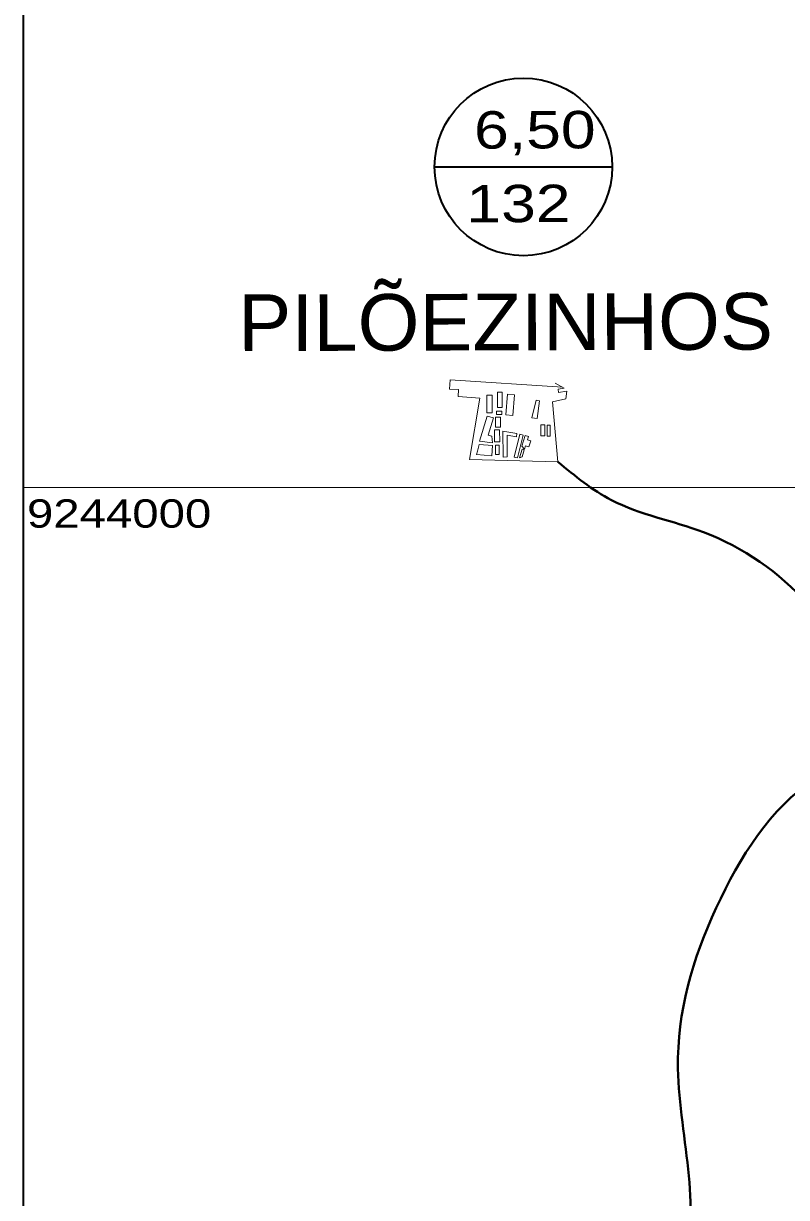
# Model space of a CAD drawing. Extents: x -4 to 42046, y -3 to 29697.
# Drawn here: x 23908 to 25194, y 13596 to 15575 of the extents above; entities that cross this region are included whole.
import ezdxf
from ezdxf.enums import TextEntityAlignment as Align

# ---------------------------------------------------------------- set-up
doc = ezdxf.new("R2010")
doc.units = 0
doc.header["$LTSCALE"] = 32
doc.linetypes.add('DOT_DASHED', pattern=[7.7, 5, -1.2, 0.3, -1.2])
for name, color, linetype, lineweight in [('1', 7, 'DOT_DASHED', 13), ('6', 7, 'Continuous', 40), ('63', 7, 'Continuous', 25), ('8', 7, 'Continuous', 35), ('9', 7, 'Continuous', 40)]:
    doc.layers.add(name, color=color, linetype=linetype, lineweight=lineweight)

msp = doc.modelspace()

# ---------------------------------------------------------------- linework, layer by layer
at = {"layer": '1', "linetype": 'Continuous'}
msp.add_lwpolyline([(24803.67, 14968.73), (24819.25, 14960.43), (24808.72, 14958.85), (24809.58, 14953.13), (24823.73, 14955.25), (24821.79, 14942.77), (24799.17, 14937.74), (24808.46, 14836.4), (24659.35, 14840.3), (24676.71, 14943.88), (24640.44, 14946.26), (24641.21, 14958.03), (24625.88, 14959.03), (24626.88, 14974.34), (24816.4, 14961.95)], dxfattribs=at)
for points in [[(24688.88, 14918.81), (24688.79, 14948.88), (24697.78, 14948.91), (24697.87, 14918.84)], [(24714.58, 14927.88), (24714.5, 14953.92), (24706.75, 14953.89), (24706.83, 14927.85)], [(24720.81, 14915.5), (24723.81, 14950.22), (24735.53, 14949.22), (24732.53, 14914.49)], [(24705.31, 14916.07), (24705.3, 14921.65), (24713.98, 14921.68), (24713.99, 14916.1)], [(24764.85, 14910.36), (24771.89, 14940.45), (24777.47, 14939.14), (24773.84, 14909.14)], [(24676.62, 14871.35), (24689.2, 14913.54), (24699.96, 14910.34), (24691.26, 14881.19), (24697.22, 14879.41), (24698.33, 14868.62)], [(24703.52, 14894.99), (24703.47, 14911.42), (24711.53, 14911.44), (24711.58, 14895.01)], [(24701.73, 14870.18), (24701.67, 14890.02), (24710.35, 14890.05), (24710.41, 14870.21)], [(24716.07, 14844.19), (24715.94, 14887.89), (24739.51, 14883.93), (24738.59, 14878.51), (24723.2, 14881.1), (24722.89, 14844.52)], [(24734.98, 14844.24), (24744.47, 14882.71), (24750.02, 14881.34), (24740.52, 14842.88)], [(24779.82, 14880.33), (24779.76, 14898.93), (24786.58, 14898.95), (24786.64, 14880.35)], [(24790.36, 14879.74), (24790.3, 14898.34), (24795.26, 14898.36), (24795.32, 14879.76)], [(24672.95, 14854.29), (24676.02, 14865.77), (24698.34, 14863.97), (24696.93, 14846.5), (24671.58, 14848.53)], [(24703.35, 14848.49), (24703.3, 14864.3), (24709.5, 14864.32), (24709.54, 14848.51)], [(24747.63, 14862.57), (24753.16, 14880.87), (24758.81, 14879.17), (24757.1, 14873.52), (24762.76, 14871.82), (24759.72, 14861.77), (24753.83, 14863.54), (24752.06, 14857.66)], [(24743.97, 14843.34), (24748.27, 14857.61), (24751.61, 14856.61), (24748.12, 14845.02)]]:
    msp.add_lwpolyline(points, close=True, dxfattribs=at)
at = {"layer": '6'}
for points in [[(25295.46, 14508.99), (25229.07, 14597.18), (25054.12, 14717.71), (24898.9, 14771.74), (24808.46, 14836.4)], [(25532.33, 14368.35), (25240.25, 14300.64), (25075.5, 14084.68), (25010.89, 13813.92), (25010.89, 13469.02), (24859.06, 13291.73), (24739.53, 13053.21), (24594.16, 12898.49)]]:
    msp.add_spline(points, degree=3, dxfattribs=at)
at = {"layer": '63', "lineweight": 13}
msp.add_line((41110.1, 14792.87), (23907.83, 14792.87), dxfattribs=at)
at = {"layer": '63', "lineweight": 35}
msp.add_lwpolyline([(41110.1, 10019.66), (23907.83, 10019.66), (23907.83, 18929.66)], dxfattribs=at)
at = {"layer": '9', "lineweight": 35}
msp.add_line((24600.72, 15333.45), (24899.98, 15333.45), dxfattribs=at)
msp.add_circle((24750.35, 15333.45), 149.63, dxfattribs=at)

# ---------------------------------------------------------------- texts
at = {"layer": '8', "width": 1.25}
msp.add_text('9244000', height=47.73, dxfattribs=at).set_placement((23913.73, 14725.38))
at = {"layer": '9', "width": 1.25}
for s, p in [('6,50 ', (24784.39, 15364.59)), ('132', (24742.11, 15240.28))]:
    msp.add_text(s, height=63, rotation=0.17, dxfattribs=at).set_placement(p, align=Align.CENTER)
at = {"layer": '9', "width": 1.05}
msp.add_text('PILÕEZINHOS', height=95.46, rotation=0.17, dxfattribs=at).set_placement((24269.91, 15022.93))

doc.saveas('drawing.dxf')
